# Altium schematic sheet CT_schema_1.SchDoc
size 543 x 506 mm
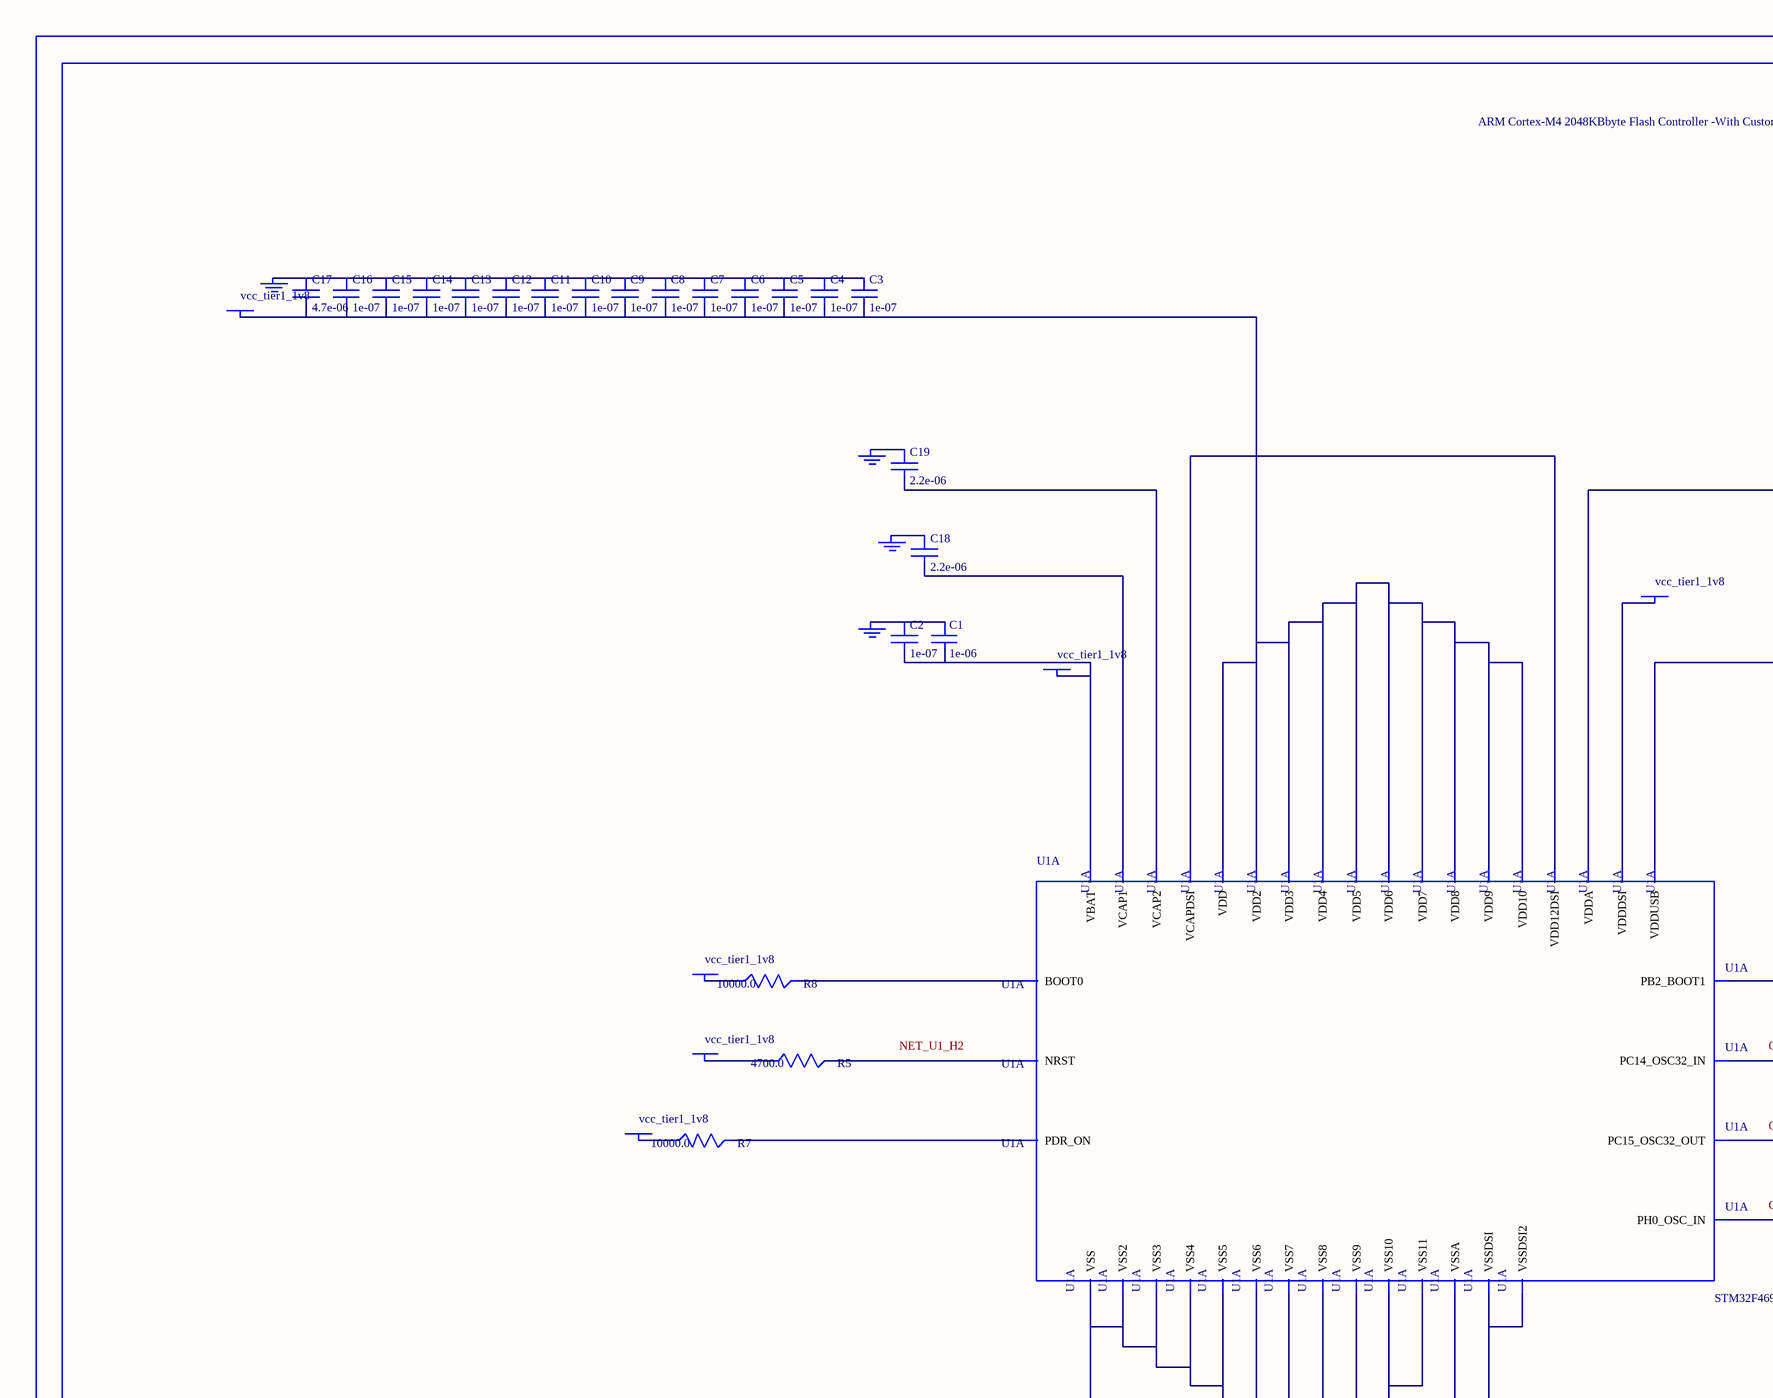
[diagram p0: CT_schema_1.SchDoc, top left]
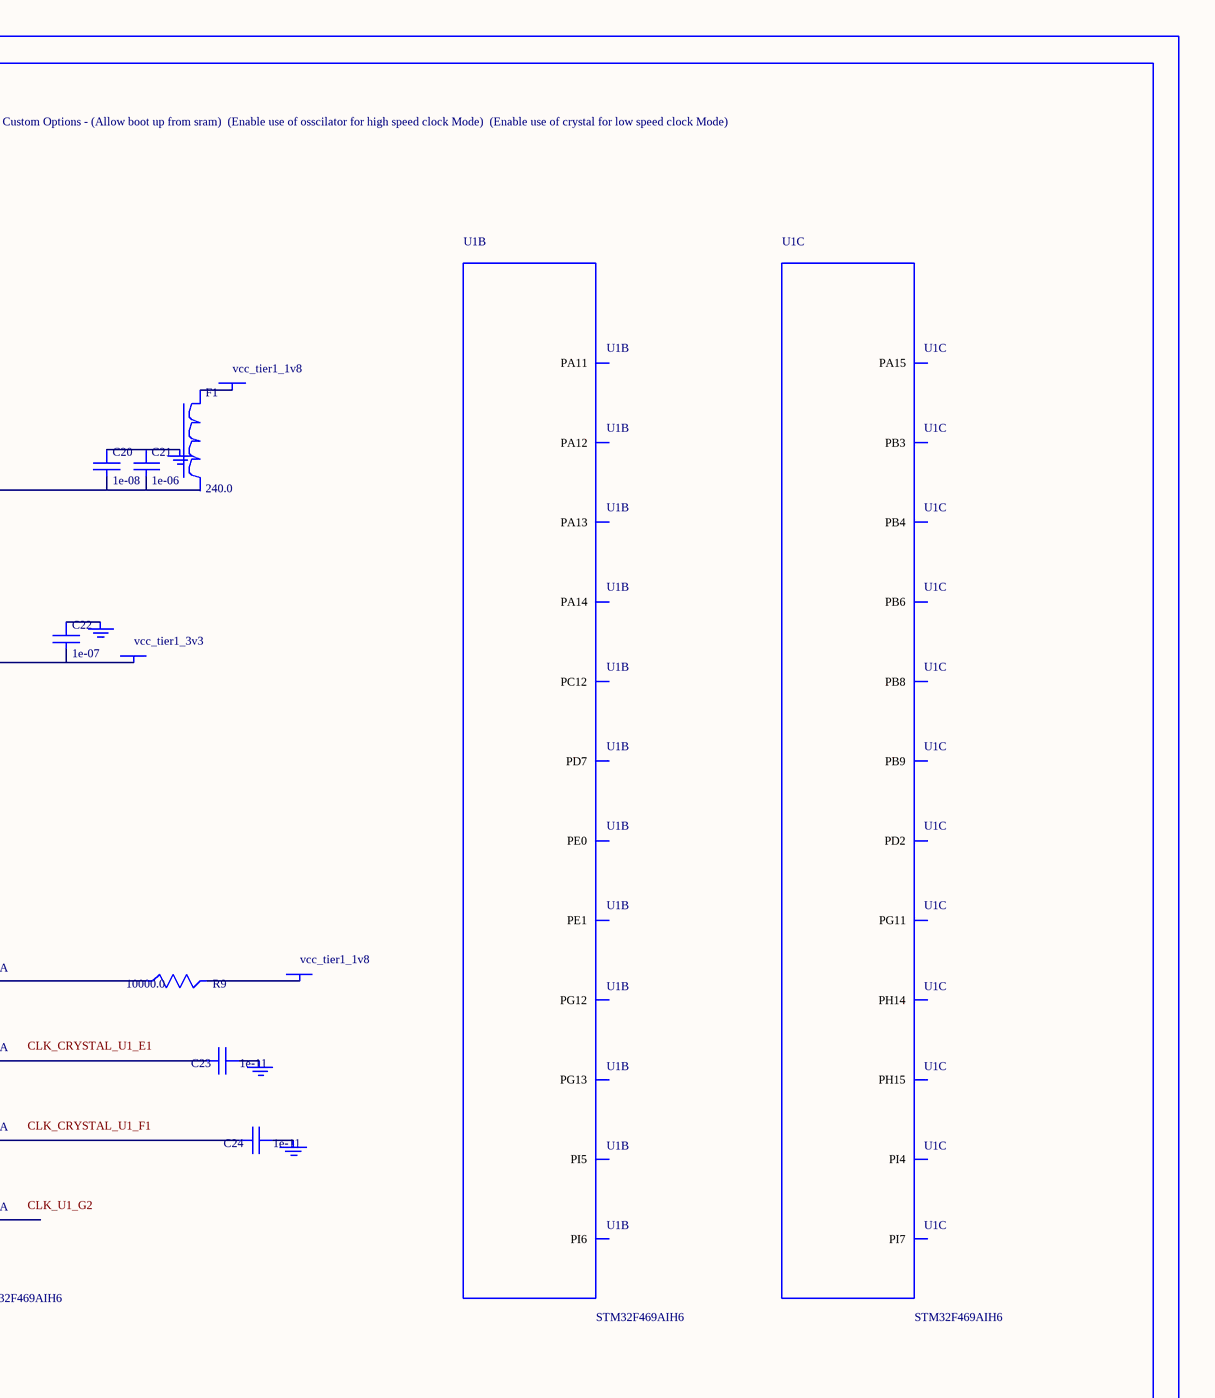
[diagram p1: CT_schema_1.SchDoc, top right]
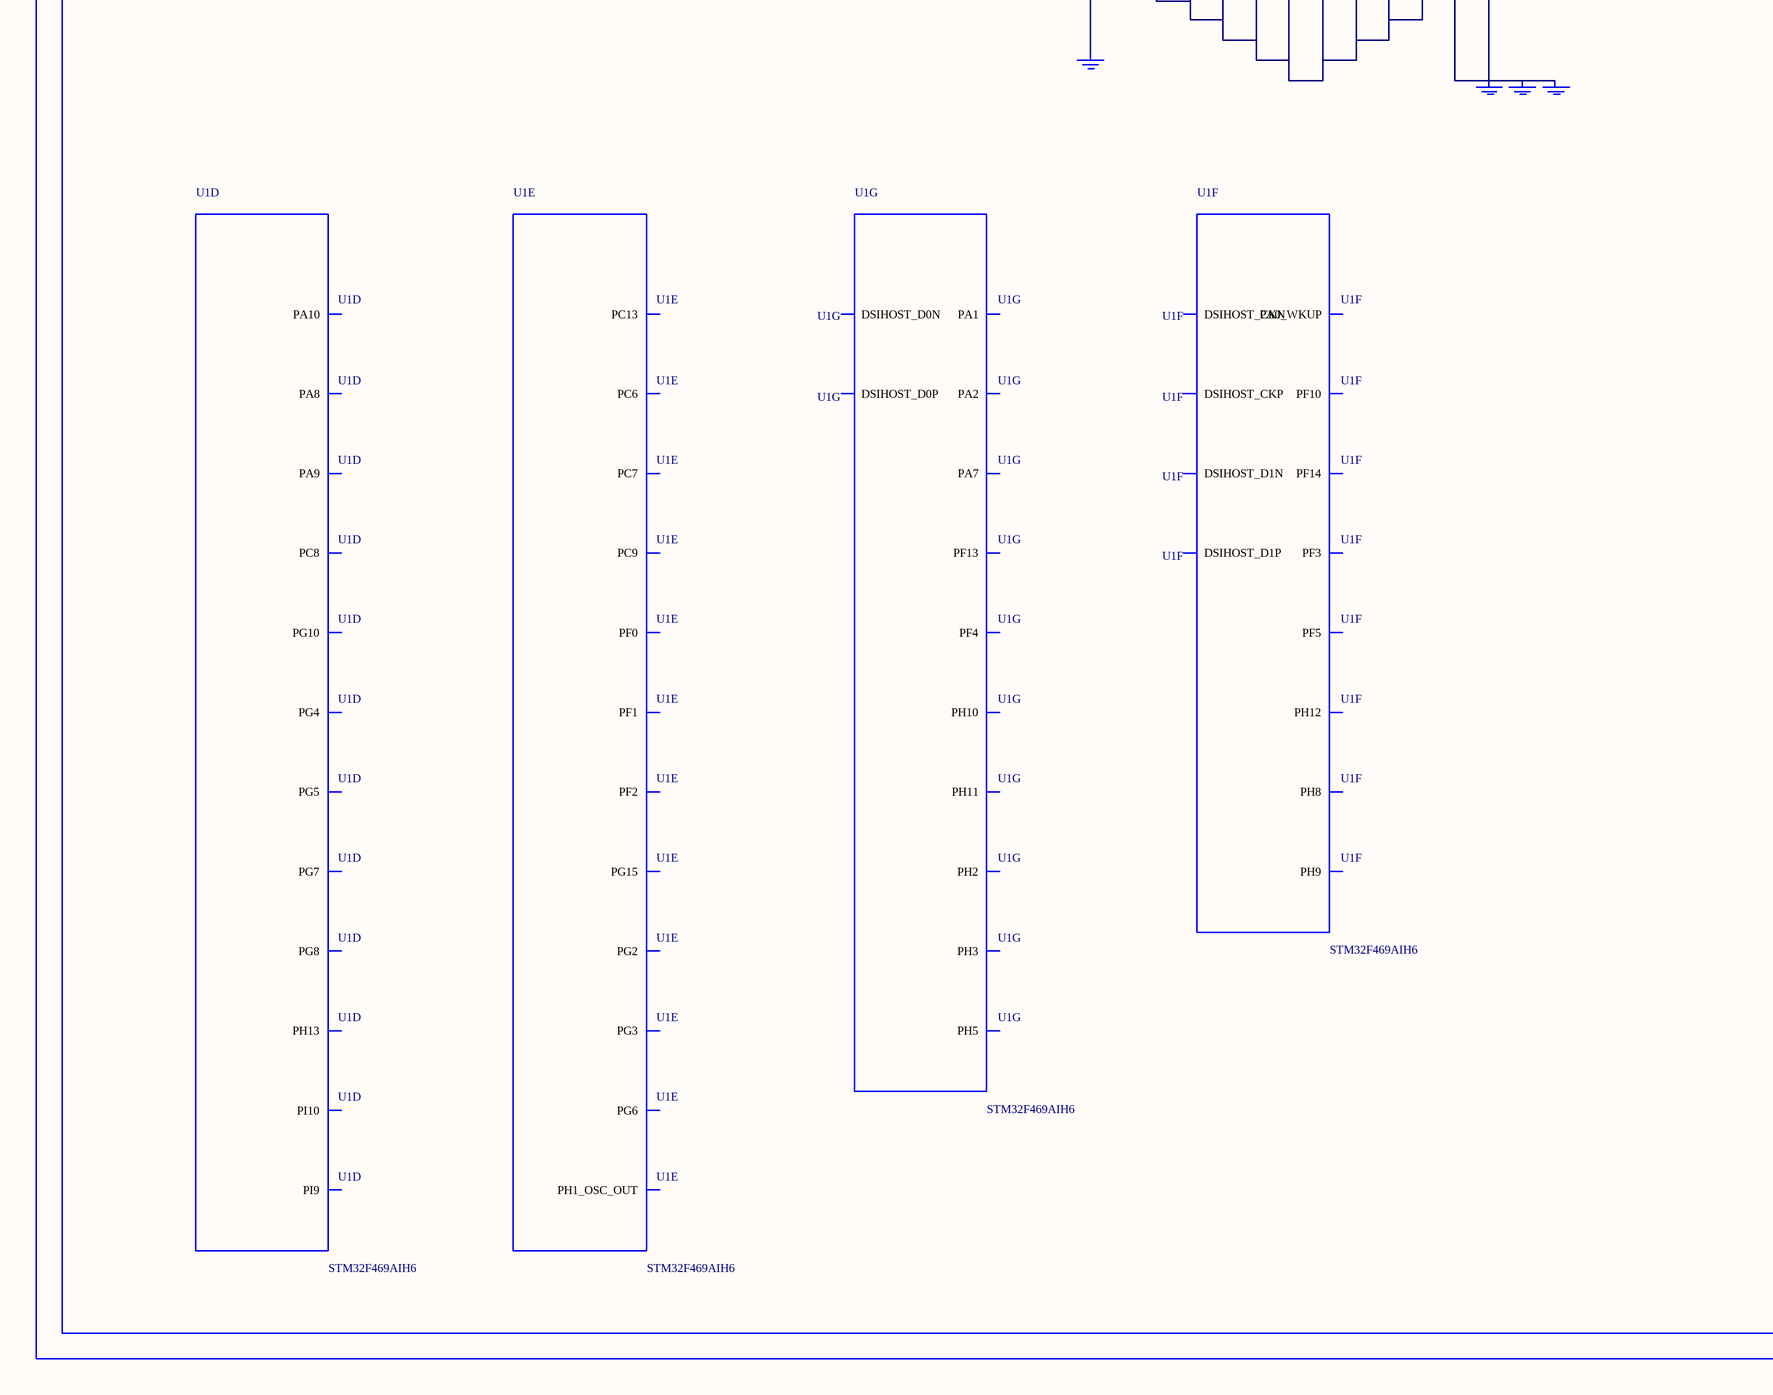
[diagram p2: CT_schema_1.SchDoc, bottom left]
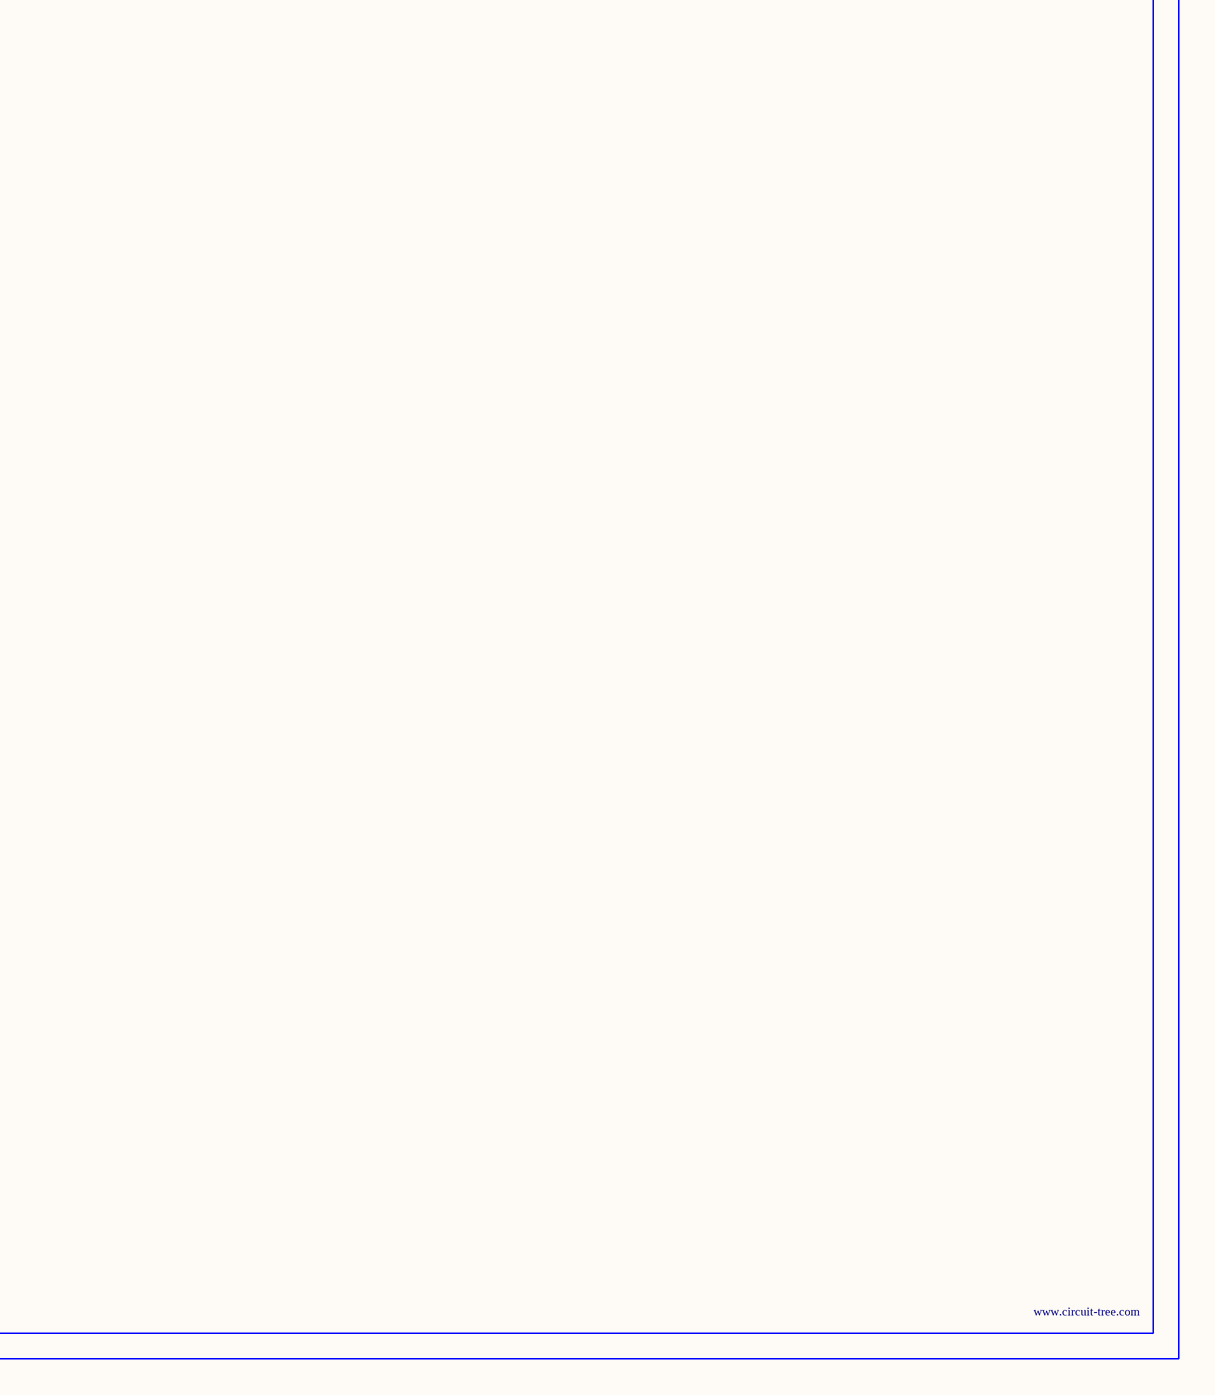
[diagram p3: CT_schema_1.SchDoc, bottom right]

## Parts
BORDER0  (no value)
C1  1e-06  [C0603]
C2  1e-07  [C0603]
C3  1e-07  [C0603]
C4  1e-07  [C0603]
C5  1e-07  [C0603]
C6  1e-07  [C0603]
C7  1e-07  [C0603]
C8  1e-07  [C0603]
C9  1e-07  [C0603]
C10  1e-07  [C0603]
C11  1e-07  [C0603]
C12  1e-07  [C0603]
C13  1e-07  [C0603]
C14  1e-07  [C0603]
C15  1e-07  [C0603]
C16  1e-07  [C0603]
C17  4.7e-06  [C0603]
C18  2.2e-06  [C0603]
C19  2.2e-06  [C0603]
C20  1e-08  [C0603]
C21  1e-06  [C0603]
C22  1e-07  [C0603]
C23  1e-11  [C0402]
C24  1e-11  [C0402]
F1  240.0  [L0603]
GND_INSTANCE_0_0  (no value)
GND_INSTANCE_0_1  (no value)
GND_INSTANCE_0_2  (no value)
GND_INSTANCE_0_3  (no value)
GND_INSTANCE_0_4  (no value)
GND_INSTANCE_0_5  (no value)
GND_INSTANCE_0_6  (no value)
GND_INSTANCE_0_7  (no value)
GND_INSTANCE_0_8  (no value)
GND_INSTANCE_0_9  (no value)
GND_INSTANCE_0_10  (no value)
GND_INSTANCE_0_11  (no value)
POWER_INSTANCE_0_0  vcc_tier1_1v8
POWER_INSTANCE_0_1  vcc_tier1_1v8
POWER_INSTANCE_0_2  vcc_tier1_1v8
POWER_INSTANCE_0_3  vcc_tier1_1v8
POWER_INSTANCE_0_4  vcc_tier1_3v3
POWER_INSTANCE_0_5  vcc_tier1_1v8
POWER_INSTANCE_0_6  vcc_tier1_1v8
POWER_INSTANCE_0_7  vcc_tier1_1v8
POWER_INSTANCE_0_8  vcc_tier1_1v8
R5  4700.0  [R0603]
R7  10000.0  [R0603]
R8  10000.0  [R0603]
R9  10000.0  [R0603]
U1  STM32F469AIH6  [UFBGA169]  (parts A,B,C,D,E,F,G of 13)

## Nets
NetC1_1: C1.1 C2.1 GND_INSTANCE_0_0.0(GND)
NetC1_2: C1.2 C2.2 POWER_INSTANCE_0_0.0(PWR) U1.E5(VBAT)
NetC3_1: C3.1 C4.1 C5.1 C6.1 C7.1 C8.1 C9.1 C10.1 C11.1 C12.1 C13.1 C14.1 C15.1 C16.1 C17.1 GND_INSTANCE_0_2.0(GND)
NetC3_2: C3.2 C4.2 C5.2 C6.2 C7.2 C8.2 C9.2 C10.2 C11.2 C12.2 C13.2 C14.2 C15.2 C16.2 C17.2 POWER_INSTANCE_0_2.0(PWR) U1.D3(VDD2) U1.D10(VDD) U1.F4(VDD3) U1.F7(VDD4) U1.G8(VDD5) U1.J4(VDD6) U1.K6(VDD8) U1.K10(VDD7) U1.L6(VDD9) U1.L9(VDD10)
NetC18_1: C18.1 GND_INSTANCE_0_3.0(GND)
NetC18_2: C18.2 U1.N9(VCAP1)
NetC19_1: C19.1 GND_INSTANCE_0_4.0(GND)
NetC19_2: C19.2 U1.D12(VCAP2)
NetC20_1: C20.1 C21.1 GND_INSTANCE_0_1.0(GND)
NetC20_2: C20.2 C21.2 U1.J3(VDDA)
NetC22_1: C22.1 GND_INSTANCE_0_5.0(GND)
NetC22_2: C22.2 POWER_INSTANCE_0_4.0(PWR) U1.G11(VDDUSB)
NetC23_1: C23.1 GND_INSTANCE_0_6.0(GND)
NetC23_2: C23.2 U1.E1(PC14_OSC32_IN)
NetC24_1: C24.1 GND_INSTANCE_0_7.0(GND)
NetC24_2: C24.2 U1.F1(PC15_OSC32_OUT)
NetF1_1: F1.1 POWER_INSTANCE_0_1.0(PWR)
NetGND_INSTANCE_0_8_0: GND_INSTANCE_0_8.0(GND) GND_INSTANCE_0_9.0(GND) GND_INSTANCE_0_10.0(GND) U1.H11(VSSDSI) U1.J2(VSSA) U1.K11(VSSDSI2)
NetGND_INSTANCE_0_11_0: GND_INSTANCE_0_11.0(GND) U1.D11(VSS) U1.E3(VSS2) U1.F5(VSS3) U1.F8(VSS4) U1.G7(VSS5) U1.G9(VSS6) U1.J1(VSS7) U1.J6(VSS9) U1.J7(VSS10) U1.J10(VSS8) U1.M9(VSS11)
NetPOWER_INSTANCE_0_3_0: POWER_INSTANCE_0_3.0(PWR) R7.1
NetPOWER_INSTANCE_0_5_0: POWER_INSTANCE_0_5.0(PWR) R8.1
NetPOWER_INSTANCE_0_6_0: POWER_INSTANCE_0_6.0(PWR) R9.2
NetPOWER_INSTANCE_0_7_0: POWER_INSTANCE_0_7.0(PWR) U1.K13(VDDDSI)
NetPOWER_INSTANCE_0_8_0: POWER_INSTANCE_0_8.0(PWR) R5.1
NetR5_2: R5.2 U1.H2(NRST)
NetR7_2: R7.2 U1.C3(PDR_ON)
NetR8_2: R8.2 U1.A5(BOOT0)
NetR9_1: R9.1 U1.L5(PB2_BOOT1)
NetU1_J11: U1.J11(VDD12DSI) U1.K12(VCAPDSI)

Not connected (* = marked no-connect by the designer): F1 2; U1 A1(PI6) A2(PI5) A3(PE1) A4(PE0) A6(PG13) A7(PG12) A8(PD7) A9(PC12) A10(PA14) A11(PA13) A12(PA12) A13(PA11) B1(PI7) B3(PI4) B5(PB3) B6(PG11) B8(PD2) B11(PA15) C4(PB9) C5(PB6) C12(PH15) C13(PH14) D4(PB8) D6(PB4) D8(PA8) D9(PH13) D13(PG8) E2(PI9) E4(PI10) E7(PG10) E8(PA9) E9(PA10) E10(PC8) E11(PG7) E12(PG5) E13(PG4) F3(PF0) F6(PG15) F9(PC6) F10(PC7) F11(PG6) F12(PG3) F13(PG2) G1(PH1_OSC_OUT) G2(PH0_OSC_IN) G3(PF1) G4(PC13) G5(PF2) G10(PC9) G12(DSIHOST_D1P) G13(DSIHOST_D1N) H1(PF10) H3(PF5) H4(PF3) H5(PF14) H8(PH8) H9(PH9) H10(PH12) H12(DSIHOST_CKP) H13(DSIHOST_CKN) J5(PA0_WKUP) J9(PH10) J12(DSIHOST_D0P) J13(DSIHOST_D0N) K1(PA1) K2(PA2) K4(PA7) K9(PH11) L1(PH3) L2(PH2) L3(PH5) L4(PF4) M4(PF13)

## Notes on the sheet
- Labels drawn without touching a wire or pin: CLK_CRYSTAL_U1_E1, CLK_CRYSTAL_U1_F1, CLK_U1_G2, NET_U1_H2

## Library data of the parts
BORDER0 = BORDER_PAGE0
C1 C21 = C0603C105K3RACTU
C2-C16 C22 = 06035C104K4Z2A
C17 = GRM188R6YA475KE15D
C18 C19 = C0603C225K8RACTU
C20 = 06035C103K4Z2A
C23 C24 = C0402C100K3GACTU
F1 = Z0603C241ASMST
GND_INSTANCE_0_0-GND_INSTANCE_0_11 = GND
POWER_INSTANCE_0_0-POWER_INSTANCE_0_8 = PWR
R5 = RC0603JR-074K7L
R7-R9 = RC0603JR-0710KL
